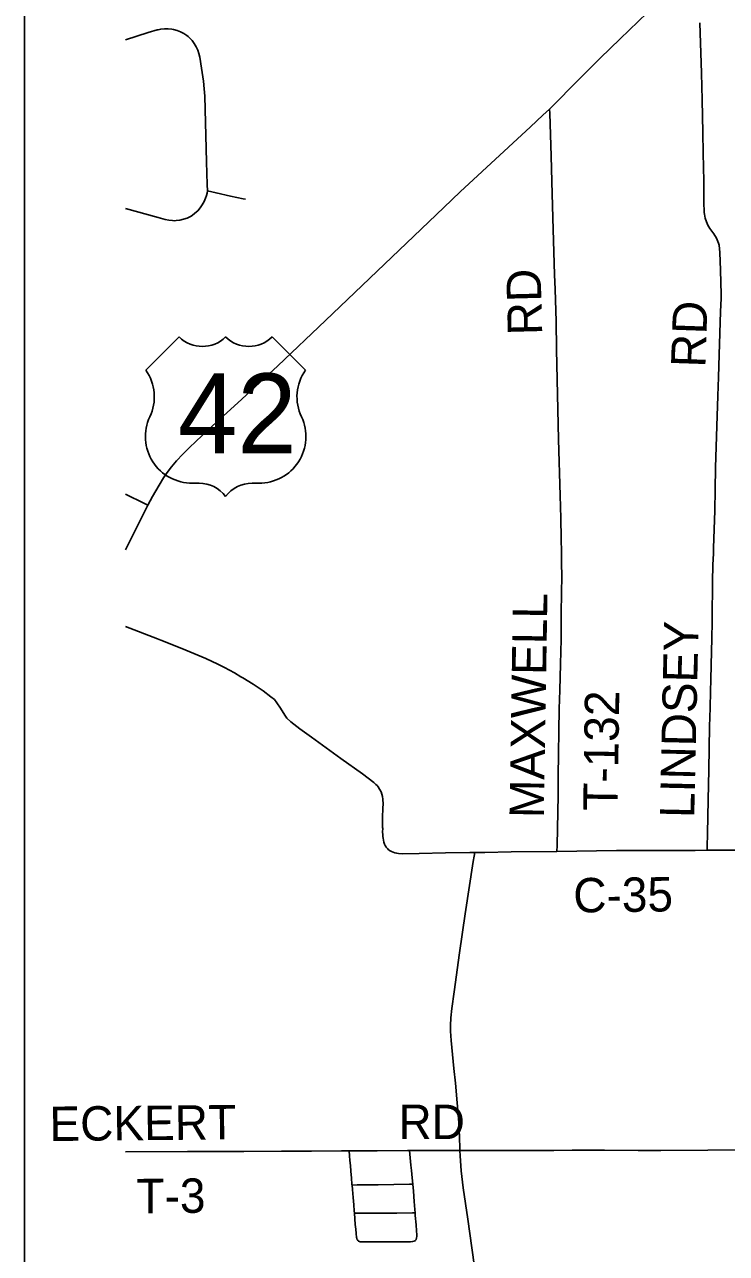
# Model space of a CAD drawing. Extents: x 40529 to 41139, y 15164 to 15584.
# Drawn here: x 40528.7 to 40563.5, y 15422.8 to 15483.8 of the extents above; entities that cross this region are included whole.
import ezdxf

# ---------------------------------------------------------------- set-up
doc = ezdxf.new("R2010")
doc.units = 0
for name, color, linetype in [('GM_X_County_Road', 7, 'Continuous'), ('GM_X_County_Road_Text', 7, 'Continuous'), ('GM_X_Township_Road', 7, 'Continuous'), ('GM_X_Township_Road_Text', 7, 'Continuous'), ('GM_X_US_Location', 7, 'Continuous'), ('GM_X_US_Route', 7, 'Continuous'), ('GM_X_US_Shield', 7, 'Continuous'), ('SC_Scratch1', 7, 'Continuous')]:
    doc.layers.add(name, color=color, linetype=linetype)

msp = doc.modelspace()

# ---------------------------------------------------------------- linework, layer by layer
at = {"layer": 'GM_X_County_Road'}
for points in [[(40533.651, 15453.923), (40535.237, 15453.317), (40535.412, 15453.254), (40536.447, 15452.841), (40537.648, 15452.341), (40538.24, 15452.067), (40538.572, 15451.899), (40539.057, 15451.627), (40539.38, 15451.429), (40539.471, 15451.38), (40539.979, 15451.072), (40540.486, 15450.735), (40540.862, 15450.451), (40541.037, 15450.316), (40541.164, 15450.15), (40541.343, 15449.887), (40541.562, 15449.529), (40541.663, 15449.389), (40541.851, 15449.209), (40542.293, 15448.864), (40542.874, 15448.444), (40543.425, 15448.046), (40544.339, 15447.39), (40545.407, 15446.625), (40545.966, 15446.196), (40546.067, 15446.1), (40546.141, 15446.039), (40546.194, 15445.973), (40546.259, 15445.868), (40546.329, 15445.728), (40546.404, 15445.501), (40546.412, 15445.361), (40546.426, 15445.116), (40546.417, 15444.946), (40546.413, 15444.814), (40546.408, 15444.569), (40546.404, 15444.303), (40546.404, 15444.123), (40546.405, 15443.966), (40546.41, 15443.917), (40546.408, 15443.743), (40546.413, 15443.603), (40546.417, 15443.515), (40546.426, 15443.432), (40546.443, 15443.336), (40546.467, 15443.236), (40546.496, 15443.145), (40546.536, 15443.063), (40546.585, 15442.988), (40546.641, 15442.922), (40546.705, 15442.864), (40546.775, 15442.814), (40546.852, 15442.772), (40546.934, 15442.736), (40547.019, 15442.707), (40547.108, 15442.684), (40547.198, 15442.67), (40547.379, 15442.665), (40548.218, 15442.675), (40549.522, 15442.708), (40550.734, 15442.727), (40550.976, 15442.728)], [(40550.976, 15442.728), (40551.479, 15442.729), (40552.783, 15442.75), (40555.05, 15442.779)], [(40555.05, 15442.779), (40558, 15442.818), (40559.3, 15442.819), (40561.904, 15442.83), (40562.496, 15442.839)], [(40562.496, 15442.839), (40562.743, 15442.842), (40563.673, 15442.836), (40564.51, 15442.842), (40566.187, 15442.85), (40568.14, 15442.858), (40569.258, 15442.865), (40571.214, 15442.863), (40573.169, 15442.857), (40575.312, 15442.834), (40577.638, 15442.839), (40578.104, 15442.84), (40578.247, 15442.84)]]:
    msp.add_lwpolyline(points, dxfattribs=at)
at = {"layer": 'GM_X_Township_Road'}
for points in [[(40562.79, 15456.993), (40562.816, 15457.546), (40562.823, 15457.812), (40562.874, 15459.676), (40562.9, 15460.704), (40562.91, 15461.822), (40562.98, 15463.871), (40563.025, 15465.362), (40563.063, 15466.293), (40563.103, 15467.408), (40563.166, 15469.551), (40563.189, 15470.202), (40563.191, 15470.389), (40563.16, 15471.608), (40563.133, 15472.48), (40563.118, 15472.665), (40563.091, 15472.846), (40563.067, 15472.932), (40563.035, 15473.015), (40562.962, 15473.188), (40562.834, 15473.404), (40562.637, 15473.671), (40562.542, 15473.834), (40562.461, 15474.003), (40562.401, 15474.182), (40562.367, 15474.37), (40562.355, 15474.463), (40562.343, 15474.992), (40562.334, 15476.016), (40562.308, 15477.408), (40562.284, 15478.43), (40562.257, 15480.056), (40562.222, 15481.378), (40562.145, 15483.864)], [(40533.651, 15483.018), (40534.774, 15483.39), (40535.221, 15483.516), (40535.268, 15483.526), (40535.401, 15483.554), (40535.582, 15483.575), (40535.765, 15483.576), (40535.947, 15483.558), (40536.037, 15483.541), (40536.212, 15483.491), (40536.382, 15483.422), (40536.545, 15483.337), (40536.698, 15483.237), (40536.77, 15483.181), (40536.837, 15483.119), (40536.961, 15482.985), (40537.069, 15482.837), (40537.161, 15482.679), (40537.237, 15482.513), (40537.294, 15482.338), (40537.335, 15482.159), (40537.432, 15481.61), (40537.525, 15480.966), (40537.563, 15480.597), (40537.585, 15480.226), (40537.68, 15476.97), (40537.709, 15475.855), (40537.726, 15475.528)], [(40555.05, 15442.779), (40555.056, 15443.065), (40555.111, 15445.575), (40555.119, 15446.505), (40555.169, 15449.856), (40555.192, 15450.766), (40555.221, 15452.058), (40555.236, 15452.314), (40555.241, 15452.442), (40555.241, 15452.6), (40555.251, 15452.866), (40555.256, 15453.098), (40555.261, 15453.487), (40555.266, 15454.73), (40555.275, 15455.445), (40555.281, 15455.854), (40555.29, 15456.175), (40555.29, 15456.653), (40555.28, 15456.845), (40555.275, 15457.604), (40555.259, 15458.29), (40555.246, 15459.3), (40555.211, 15460.425), (40555.128, 15463.206), (40555.029, 15467.673), (40555.009, 15469.069), (40554.96, 15470.648), (40554.932, 15471.392), (40554.872, 15473.624), (40554.815, 15475.393), (40554.761, 15477.254), (40554.691, 15479.394), (40554.681, 15479.591)], [(40533.651, 15474.658), (40535.27, 15474.214), (40535.629, 15474.114), (40535.81, 15474.077), (40535.993, 15474.056), (40536.084, 15474.054), (40536.176, 15474.058), (40536.357, 15474.084), (40536.537, 15474.129), (40536.711, 15474.188), (40536.877, 15474.267), (40536.955, 15474.313), (40537.102, 15474.423), (40537.238, 15474.548), (40537.36, 15474.686), (40537.463, 15474.837), (40537.549, 15474.999), (40537.626, 15475.17), (40537.673, 15475.311), (40537.707, 15475.423), (40537.726, 15475.528)], [(40537.726, 15475.528), (40538.147, 15475.434), (40538.855, 15475.279), (40539.491, 15475.145), (40539.6, 15475.123)], [(40533.651, 15460.489), (40534.594, 15460.026), (40534.768, 15459.94)], [(40562.496, 15442.839), (40562.501, 15442.999), (40562.521, 15443.665), (40562.544, 15445.341), (40562.581, 15446.827), (40562.621, 15448.965), (40562.645, 15449.894), (40562.67, 15450.731), (40562.683, 15451.289), (40562.707, 15452.033), (40562.73, 15453.337), (40562.757, 15454.167), (40562.769, 15456.319), (40562.782, 15456.819), (40562.79, 15456.993)], [(40550.241, 15427.94), (40550.238, 15428.054), (40550.227, 15428.589), (40550.181, 15429.329), (40550.019, 15431.277), (40549.946, 15432.011), (40549.806, 15433.399), (40549.78, 15433.865), (40549.778, 15434.146), (40549.795, 15434.519), (40549.839, 15434.984), (40549.948, 15435.816), (40550.223, 15437.754), (40550.508, 15439.69), (40550.895, 15442.27), (40550.944, 15442.546), (40550.976, 15442.728)], [(40533.651, 15427.874), (40536.73, 15427.899), (40537.45, 15427.9)], [(40537.45, 15427.9), (40539.523, 15427.9), (40541.389, 15427.917), (40542.882, 15427.919), (40544.37, 15427.934), (40544.742, 15427.933)], [(40544.742, 15427.933), (40546.142, 15427.932), (40547.634, 15427.94), (40547.741, 15427.94), (40549.313, 15427.945), (40550.241, 15427.94)], [(40544.742, 15427.933), (40544.763, 15427.678), (40544.778, 15427.454), (40544.806, 15427.196), (40544.83, 15426.919), (40544.859, 15426.567), (40544.886, 15426.27), (40544.89, 15426.232), (40544.911, 15426.011), (40544.942, 15425.621), (40544.971, 15425.25), (40544.997, 15424.953), (40545.006, 15424.837), (40545.028, 15424.562), (40545.05, 15424.283), (40545.073, 15424.042), (40545.091, 15423.838), (40545.115, 15423.631), (40545.123, 15423.593), (40545.135, 15423.554), (40545.154, 15423.516), (40545.181, 15423.482), (40545.215, 15423.454), (40545.253, 15423.436), (40545.293, 15423.425), (40545.325, 15423.42), (40545.371, 15423.416), (40545.783, 15423.416), (40546.194, 15423.419), (40546.958, 15423.422), (40547.349, 15423.416), (40547.668, 15423.417), (40547.789, 15423.423), (40547.893, 15423.433), (40547.954, 15423.445), (40547.977, 15423.454), (40547.994, 15423.461), (40548.012, 15423.473), (40548.03, 15423.487), (40548.043, 15423.502), (40548.057, 15423.521), (40548.068, 15423.537), (40548.077, 15423.559), (40548.084, 15423.584), (40548.092, 15423.62), (40548.099, 15423.684), (40548.102, 15423.772), (40548.088, 15423.96), (40548.063, 15424.257), (40548.024, 15424.719), (40548.014, 15424.85), (40548.002, 15425.016), (40547.968, 15425.423), (40547.931, 15425.925), (40547.9, 15426.275), (40547.871, 15426.59), (40547.84, 15426.947), (40547.811, 15427.225), (40547.774, 15427.577), (40547.741, 15427.94)], [(40550.241, 15427.94), (40550.336, 15427.94), (40553.505, 15427.943), (40554.904, 15427.949), (40555.8, 15427.957)], [(40551.816, 15412.907), (40551.854, 15413.01), (40551.934, 15413.273), (40552.018, 15413.614), (40552.063, 15413.945), (40552.08, 15414.223), (40552.079, 15414.502), (40552.058, 15414.872), (40551.996, 15415.521), (40551.859, 15416.63), (40551.739, 15417.458), (40551.657, 15417.913), (40551.351, 15419.556), (40551.213, 15420.383), (40551.041, 15421.58), (40550.631, 15424.534), (40550.405, 15426.102), (40550.306, 15426.935), (40550.252, 15427.686), (40550.241, 15427.94)], [(40555.8, 15427.957), (40556.486, 15427.963), (40557.414, 15427.965), (40559.071, 15427.945), (40559.643, 15427.945), (40560.203, 15427.95), (40562.534, 15427.967), (40564.585, 15427.979), (40567.939, 15428.012), (40569.711, 15428.026), (40570.923, 15428.047), (40572.787, 15428.051), (40574.462, 15428.039), (40575.674, 15428.04), (40576.98, 15428.054), (40577.37, 15428.062), (40577.508, 15428.064)], [(40544.89, 15426.232), (40545.139, 15426.236), (40545.213, 15426.237), (40545.566, 15426.242), (40546.179, 15426.247), (40547.74, 15426.272), (40547.9, 15426.275)], [(40545.006, 15424.837), (40545.138, 15424.838), (40545.677, 15424.838), (40546.756, 15424.841), (40547.108, 15424.84), (40547.887, 15424.849), (40548.014, 15424.85)]]:
    msp.add_lwpolyline(points, dxfattribs=at)
at = {"layer": 'GM_X_US_Route'}
msp.add_lwpolyline([(40533.651, 15457.736), (40534.649, 15459.715), (40534.768, 15459.94), (40534.998, 15460.375), (40535.32, 15460.938), (40535.536, 15461.308), (40535.715, 15461.56), (40535.938, 15461.855), (40536.178, 15462.139), (40536.493, 15462.482), (40536.822, 15462.81), (40537.776, 15463.701), (40539.428, 15465.209), (40541.203, 15466.859), (40543.571, 15469.107), (40547.961, 15473.283), (40549.436, 15474.709), (40550.248, 15475.478), (40553.734, 15478.71), (40554.351, 15479.28), (40554.681, 15479.591), (40556.201, 15481.125), (40557.19, 15482.109), (40558.194, 15483.069), (40559.52, 15484.361)], dxfattribs=at)
at = {"layer": 'GM_X_US_Shield'}
for p, q in [((40536.315, 15468.292), (40534.667, 15466.644)), ((40542.577, 15466.644), (40540.929, 15468.292)), ((40536.974, 15461.041), (40537.304, 15461.041)), ((40539.94, 15461.041), (40540.27, 15461.041))]:
    msp.add_line(p, q, dxfattribs=at)
for centre, radius, start, end in [((40537.469, 15469.468), 1.648, 225.573, 314.427), ((40539.776, 15469.468), 1.648, 225.573, 314.427), ((40532.777, 15465.32), 2.307, 334.54712, 35.00093), ((40544.467, 15465.32), 2.307, 144.99907, 205.45288), ((40536.948, 15463.348), 2.307, 154.83192, 270.63826), ((40540.296, 15463.348), 2.307, 269.36174, 25.16808), ((40537.304, 15459.393), 1.648, 36.8699, 90), ((40539.94, 15459.393), 1.648, 90, 143.1301)]:
    msp.add_arc(centre, radius, start, end, dxfattribs=at)
at = {"layer": 'SC_Scratch1'}
msp.add_lwpolyline([(40528.651, 15584.313), (41138.651, 15584.313), (41138.651, 15164.313), (40528.651, 15164.313)], close=True, dxfattribs=at)

# ---------------------------------------------------------------- texts
at = {"layer": 'GM_X_County_Road_Text'}
msp.add_text('C-35', height=1.7063, rotation=0.69324, dxfattribs=at).set_placement((40555.871, 15439.745))
at = {"layer": 'GM_X_Township_Road_Text'}
for s, rotation, p in [('RD', 91.48055, (40554.325, 15468.396)), ('RD', 88.02616, (40562.409, 15466.757)), ('MAXWELL', 89.06643, (40554.4, 15444.421)), ('LINDSEY', 88.71474, (40561.858, 15444.423)), ('T-132', 89.1551, (40558.058, 15444.78)), ('ECKERT', 0.52385, (40529.892, 15428.415)), ('RD', 0.00001, (40547.191, 15428.515)), ('T-3', 0.47623, (40534.206, 15424.832))]:
    msp.add_text(s, height=1.7063, rotation=rotation, dxfattribs=at).set_placement(p)
at = {"layer": 'GM_X_US_Location'}
for s in ['0', '/']:
    msp.add_text(s, height=0.00568, dxfattribs=at).set_placement((40538.62, 15464.47))
msp.add_text('42', height=0.00568, rotation=0.00001, dxfattribs=at).set_placement((40537.447, 15463.294))
at = {"layer": 'GM_X_US_Shield'}
msp.add_text('42', height=3.9551, dxfattribs=at).set_placement((40536.259, 15462.524))

doc.saveas('drawing.dxf')
